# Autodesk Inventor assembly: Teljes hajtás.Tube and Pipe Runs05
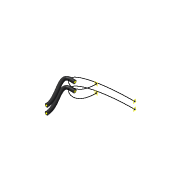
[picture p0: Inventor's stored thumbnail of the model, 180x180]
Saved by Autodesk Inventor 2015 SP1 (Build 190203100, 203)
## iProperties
Name: ISO 2531 - Flanged Ductile Iron Pipe and Fittings
ActiveState: False
PipeType: Rigid Pipe
RoutePreview: Solid
Material: UnInitValue
Standard: UnInitValue
FittingMaterial: UnInitValue
FittingStandard: UnInitValue
RouteDirection90: True
RouteDirection45: True
DiameterType: Nominal
Diameter: M40
Schedule: PN10
Ending: UnInitValue
IntermediateSegmentsMin: 1000.000 mm
IntermediateSegmentsMax: 9000.000 mm
IntermediateSegmentsInc: 10.000 mm
TerminationSegmentsMin: 1000.000 mm
TerminationSegmentsMax: 9000.000 mm
TerminationSegmentsInc: 10.000 mm
SolidRoutePreviewColor: 12632064
PipingComponentColor: As Material
PipeKey: v3#f52fbdcb-ece8-4303-8b76-5dbe8c7f2f9c#16
Elbow90Key: v3#451ae64e-c79d-4cba-b533-c09b8090ecb2#1
Elbow45Key: v3#81684a3f-f2a4-4fe6-95b1-f067ddead22f#1
_ComponentInfo: <CS><C N="Pipe" R="2.700000" IR="2.000000" PL="PL" PN="ISO 2531 Pipe with Integrally Cast Flanges DN40 PN 10"><CO N="1"><FE V="0"/><FD V="0"/><ET  V="Flanged"/>
BendRadius: UnInitValue
CategoryName: UnInitValue
DefaultBendRadius: UnInitValue
EndFittingKey: UnInitValue
FlangeKey: UnInitValue
Gap: UnInitValue
GasketKey: UnInitValue
IsButtWelded: UnInitValue
IsFlanged: UnInitValue
MixedUnits: UnInitValue
RoundUpValue: UnInitValue
ShowGap: UnInitValue
StartFittingKey: UnInitValue
SuppressEndFitting: UnInitValue
SuppressStartFitting: UnInitValue
UseFlangsForCouplings: UnInitValue
UseSubASM: UnInitValue
Name: Hydraulic Hose - SAE Flanged Connection
PipeType: Flexible Hose
RouteDirection90: UnInitValue
RouteDirection45: UnInitValue
Diameter: 1/2
Schedule: ID=0.5
OD: 2.235200000000000e+000
ID: 1.270000000000000e+000
IntermediateSegmentsMin: UnInitValue
IntermediateSegmentsMax: UnInitValue
IntermediateSegmentsInc: UnInitValue
TerminationSegmentsMin: UnInitValue
TerminationSegmentsMax: UnInitValue
TerminationSegmentsInc: UnInitValue
RoundUpValue: 0.125 in
PipeKey: v3#d489867e-ac9b-47ea-b952-0a1b885f66be#4
CouplingKey: UnInitValue
Elbow90Key: UnInitValue
Elbow45Key: UnInitValue
_ComponentInfo: <CS><C N="Pipe" R="1.117600" OR="1.117600" IR="0.635000" PL="PL" PartType="" SymKey="" PN="Parker Hydraulic Hose - No Skive 1/2"><CO N="1"><FE V="0"/><FD V="0"/
BendRadius: 0.500 in
StartFittingKey: v3#933069c9-73b6-4141-af99-628d4a97b2c2#1
EndFittingKey: v3#933069c9-73b6-4141-af99-628d4a97b2c2#1
SuppressStartFitting: False
SuppressEndFitting: False
UseSubASM: True
Name: Hydraulic Hose - Female Taper Thread
StartFittingKey: v3#cc3bd835-95a2-497d-9893-176cd9c426f6#7
EndFittingKey: v3#cc3bd835-95a2-497d-9893-176cd9c426f6#7
Name: JIS G 3458/JIS B 2316 -  Welded Steel Pipe and Fittings
Schedule: 80
IntermediateSegmentsMin: 60.000 mm
IntermediateSegmentsMax: 5000.000 mm
IntermediateSegmentsInc: 1.000 mm
TerminationSegmentsMin: 60.000 mm
TerminationSegmentsMax: 5000.000 mm
TerminationSegmentsInc: 1.000 mm
PipeKey: v3#da14b0ab-0b36-4851-8d66-8c9cd0bcbe86#23
CouplingKey: v3#12b64993-10e6-4915-8315-0c0cce209ad0#8
Elbow90Key: v3#1f65ece3-c41a-48d4-8661-909ed34ade86#8
Elbow45Key: v3#28e76e79-e22c-40ab-8be2-ff545b1407c5#8
_ComponentInfo: <CS><C N="Pipe" R="2.430000" IR="1.920000" PL="PL" PN="JIS G 3458 Pipe 40 A x Sch 80"><CO N="1"><FE V="0"/><FD V="1"/><ET V="Welded"/><NS  V="M40"/><MA V="0.000
Name: ASTM A53/A53M-ASME B16.11 - Welded Steel Pipe
Material: Steel
Standard: ASTM A 53/A 53M
FittingMaterial: Steel
FittingStandard: ASME B16.11
Schedule: 40
OD: Undefined
ID: Undefined
IntermediateSegmentsMin: 1.000 in
IntermediateSegmentsMax: 200.000 in
IntermediateSegmentsInc: 0.100 in
TerminationSegmentsMin: 1.000 in
TerminationSegmentsMax: 200.000 in
TerminationSegmentsInc: 0.100 in
PipeKey: v3#4ce5e9fa-6da0-4801-ac02-ee7a0fb518d6#7
CouplingKey: v3#ed415c76-4cec-44a3-ba67-72e47bf70384#4
Elbow90Key: v3#82a08401-12d7-413b-b7f9-9cf3b607be7b#4
Elbow45Key: v3#2e5fd082-3851-4eb0-bde1-6c7078a7d72b#4
_ComponentInfo: <CS><C N="Pipe" R="1.066800" IR="0.789940" PL="PL" PN="ASTM A 53/A 53M Pipe 1/2 - Schedule 40"><CO N="1"><FE V="0"/><FD V="0"/><ET V="Welded"/><NS  V="1/2"/><MA
Diameter: 6
Elbow90Key: v3#97ecdcaf-8aa3-4fb0-8b6a-3da783de2ad5#108
Gap: 0.062 inch
ID: UnInitValue
IntermediateSegmentsInc: 0.00001 in
IntermediateSegmentsMax: 200 inch
IntermediateSegmentsMin: 3 inch
IsButtWelded: True
IsFlanged: False
Name: ASTM A 53/A-ASME B16.9 - Steel Butt Welded Pipe
OD: UnInitValue
PipeKey: v3#4ce5e9fa-6da0-4801-ac02-ee7a0fb518d6#77
RouteDirection45: False
ShowGap: True
TerminationSegmentsInc: 0.00001 in
TerminationSegmentsMax: 200 inch
TerminationSegmentsMin: 3 inch
_ComponentInfo: <CS><C N="Elbow90" ER="15.240000" S1="15.240000" S2="15.240000" D1="0.000000" D2="0.000000" PartType="fitting" SymKey="ELBW"><CO N="1"><FE V="2"/><FD V="0"/><ET
MixedUnits: False
Created: 2013-02
Part Number: Teljes hajtás.Tube and Pipe Runs05
Document SubType Name: Tube & Pipe
Designer: Marci
Manufacturer: Standard
Standards Organization: Custom
Angle: 92.00 deg
Diameter: 1
Elbow45Key: v3#bf26aa2a-f3dd-474c-8758-922a145c2b02#15
Elbow90Key: v3#3e93288f-9bb7-4e46-9d6b-544f8c20ca1c#3
ElbowCustomKey: v3#1f3bd44a-47ab-42f9-b3e0-74afa0c3f0ca#3
Gap: 0.094 in
IntermediateSegmentsMin: 2.000 in
IsSelfDraining: True
Name: ASME BPE - Butt Welded
PipeKey: v3#b10c956f-6fc6-429e-8056-0864a8581764#35
Schedule: ID=0.87
TerminationSegmentsMin: 2.000 in
_ComponentInfo: <CS><C N="Pipe" R="1.270000" OR="1.270000" IR="1.104900" PL="PL" PartType="pipe" SymKey="" PN="ASTM A 269 Tube with Welded ends 1 x 0.87"><CO N="1"><FE V="2"/><
Elbow90Key: v3#6a678020-d9d9-4685-bba9-906b9a167083#10
FlangeKey: v3#c11442d2-c568-438f-a870-8ac9b5b636cb#10
GasketKey: v3#2a41914c-f5fb-4682-9c6a-1870d826d3d0#23
IntermediateSegmentsInc: 0.1 inch
IsButtWelded: False
IsFlanged: True
Name: ASTM A 53/A-ASME B16.5 - Flanged Steel Threaded Pipe
PipeKey: v3#c5bd7d28-cdb3-4507-9f3d-c2787d93fe8a#40
TerminationSegmentsInc: 0.1 inch
_ComponentInfo: <CS><C N="Elbow90" ER="21.590000" S1="21.590000" S2="21.590000" D1="0.000000" D2="0.000000" PartType="fitting" SymKey="ELFL"><CO N="1"><FE V="2"/><FD V="1"/><ET
ElbowCustomKey: UnInitValue
IsSelfDraining: False
Name: ASME B36.10M-ASME B16.11 - Steel Threaded Pipe
Material: Wrought Steel
Standard: ASME B36.10M
Schedule: 30
OD: 2.1336
ID: 1.651
PipeKey: v3#4a736116-503a-44ad-a922-868ac6b46736#1
CouplingKey: v3#52ad3977-2b89-4007-a6a6-7626bac0ae85#4
Elbow90Key: v3#160eac10-3e6f-4b5c-839c-61eee0d373dc#4
Elbow45Key: v3#5c2ab816-abcb-49a6-a106-4733af000f51#4
_ComponentInfo: <CS><C N="Pipe" R="1.066800" IR="0.825500" PL="PL" PN="ASME B36.10M Pipe with Threaded Ends 1/2 - Schedule 30"><CO N="1"><FE V="0"/><FD V="1"/><ET  V="Threaded"
Name: DIN 2458/DIN 2605 - Welded Steel Pipe and Fittings
Schedule: ID=30.7
PipeKey: v3#dcef2839-8903-4c98-a96c-b861f5d9bb7f#98
Elbow90Key: v3#ace818b0-7b7c-4ad9-b19c-6da358a202c1#17
Elbow45Key: v3#97879d80-057e-491b-840b-74a9b3a7cf63#17
_ComponentInfo: <CS><C N="Pipe" R="2.415000" IR="1.535000" PL="PL" PN="DIN 2458 Pipe 48.3 x 8.8"><CO N="1"><FE V="2"/><FD V="0"/><ET V="Welded"/><NS V="M40"/><MA  V="0.000000"/
Name: Hydraulic Hose - Male Taper Thread
StartFittingKey: v3#c8250148-a7b6-458b-b7bd-3b56763ca7cc#13
EndFittingKey: v3#c8250148-a7b6-458b-b7bd-3b56763ca7cc#13
Name: JIS G 3442/JIS B 2301 Threaded Steel Pipe and Iron Fittings
Schedule: ID=16.1
IntermediateSegmentsMin: 20.000 mm
TerminationSegmentsMin: 20.000 mm
PipeKey: v3#9964fba4-9d5a-4d75-85a8-e38022ccdce1#2
CouplingKey: v3#181262db-c004-4877-bc40-c64b931a44f6#3
Elbow90Key: v3#6c92b367-65e9-486b-b952-db434ae2548d#3
Elbow45Key: v3#960407aa-00b9-4d72-aae7-d50595845cfd#3
_ComponentInfo: <CS><C N="Pipe" R="1.085000" IR="0.805000" PL="PL" PN="JIS G 3442 Pipe with Threaded Ends 21.7 x 2.8"><CO N="1"><FE V="0"/><FD V="1"/><ET V="Threaded"/><NS V="1
Name: ASTM B 88-ASME B16.22 - Soldered Copper Tubing
PipeType: Tubing
Material: Copper
Standard: ASTM B 88
FittingMaterial: *
FittingStandard: ASME B16.22
Schedule: L
IntermediateSegmentsMin: 0.000 in
IntermediateSegmentsMax: 100.000 in
TerminationSegmentsMin: 0.000 in
TerminationSegmentsMax: 100.000 in
SolidRoutePreviewColor: 49344
PipeKey: v3#44b182c9-4bce-4825-bb4d-596143122252#7
CouplingKey: v3#0dc1ae02-7bbf-4ccf-8498-581434b0a765#3
_ComponentInfo: <CS><C N="Pipe" R="0.793750" IR="0.692150" PL="PL" PN="ASTM B 88 Tube 1/2 - Type L"><CO N="1"><FE V="0"/><FD V="0"/><ET V="Soldered"/><NS V="1/2"/><MA V="2.5400
DefaultBendRadius: 2.000 in
Name: JIS K 6741/JIS K 6739 - Jointed PVC-U Pipe and Fittings
Schedule: VP
IntermediateSegmentsMax: 2500.000 mm
TerminationSegmentsMax: 2500.000 mm
PipeKey: v3#45338dd0-af69-48c0-a2ed-8ade33a08701#5
CouplingKey: v3#eaa8de87-dc67-4eca-ba7e-4267a30f8f7f#2
Elbow90Key: v3#c4513a61-3106-4a78-baf9-a1badd100245#2
Elbow45Key: v3#2769403e-a4fd-4a4c-8e4c-659ea845bd78#2
_ComponentInfo: <CS><C N="Pipe" R="2.400000" IR="2.040000" PL="PL" PN="JIS K 6741 Pipe VP 40"><CO N="1"><FE V="0"/><FD V="1"/><ET V="Jointed"/><NS V="M40"/><MA  V="4.000000"/><
Name: ISO 7598/ISO 49 - Threaded Steel Pipe with Iron Fittings
IntermediateSegmentsMin: 50.800 mm
IntermediateSegmentsMax: 5080.000 mm
IntermediateSegmentsInc: 2.540 mm
TerminationSegmentsMin: 50.800 mm
TerminationSegmentsMax: 5080.000 mm
TerminationSegmentsInc: 2.540 mm
PipeKey: v3#1052637f-74b5-47f4-adeb-d4e8d3fa53b8#1
CouplingKey: v3#7e56b2cb-a132-4546-b8a7-a14538454b94#3
Elbow90Key: v3#b72bb08b-ad33-47cc-a03d-7f3d76c6616b#3
Elbow45Key: v3#a96c5204-26e4-4bb2-b8f1-f0623fbc94bb#2
_ComponentInfo: <CS><C N="Pipe" R="1.065000" IR="0.805000" PL="PL" PN="ISO 7598 Tube with Threaded Ends DN15"><CO N="1"><FE V="0"/><FD V="1"/><ET V="Threaded"/><NS V="1/2"/><MA
FlangeKey: v3#24991861-26e3-4c21-a713-f46e314eddd5#10
IntermediateSegmentsMin: 3.000 in
Name: ASTM A 53/A 53M - Butt Welded/Flanged Steel Pipe
TerminationSegmentsMin: 3.000 in
UseFlangsForCouplings: False
_ComponentInfo: <CS><C N="Pipe" R="8.413750" OR="8.413750" IR="7.702550" PL="PL" PartType="pipe" SymKey="" PN="ASTM A 53/A 53M Pipe 6 - Schedule 40"><CO N="1"><FE V="2"/><FD V=
Name: Hydraulic Hose - Female Thread - Swivel
StartFittingKey: v3#c5e461f5-5e73-4f2e-8c1e-4358d4d6f46c#4
EndFittingKey: v3#c5e461f5-5e73-4f2e-8c1e-4358d4d6f46c#4
Name: ASTM D 1785-ASTM D 2466 - Jointed PVC Pipe and Fittings
Material: PVC-Piping
Standard: ASTM D 1785
FittingMaterial: PVC-Piping
FittingStandard: ASTM D 2466
PipeKey: v3#4bf12049-4375-491b-8f13-d4ee0c517c57#1
CouplingKey: v3#29993622-4c6a-437e-8b8c-43a0846f8735#1
Elbow90Key: v3#25d2a8db-6517-4627-a5a4-9d27e4d26b9b#1
Elbow45Key: v3#d7b5d569-4a12-4d65-ba55-12203d6ac7ed#1
_ComponentInfo: <CS><C N="Pipe" R="1.066800" IR="0.789940" PL="PL" PN="ASTM D 1785 Pipe 1/2 - Schedule 40"><CO N="1"><FE V="0"/><FD V="0"/><ET V="Jointed"/><NS  V="1/2"/><MA V=
Name: DIN 2458/DIN EN 10242 - Threaded Steel Pipe and Iron Fittings
Schedule: ID=12.3
PipeKey: v3#d689fd5f-ac5a-46d7-a883-3089b2f6e0a4#28
CouplingKey: v3#d2599e7a-1865-48da-a234-5418a1cd5dfe#3
Elbow90Key: v3#9fba244e-81ed-4fc6-a9ac-7eb372fa3ffe#3
Elbow45Key: v3#6ce5b1be-37aa-4928-b23a-0df64e6ddf38#2
_ComponentInfo: <CS><C N="Pipe" R="1.065000" IR="0.615000" PL="PL" PN="DIN 2458 Pipe with Threaded Ends 21.3 x 4.5"><CO N="1"><FE V="0"/><FD V="1"/><ET V="Threaded"/><NS V="1/2
count: 29
Refkey_Axis1_Context: 2|0|0|0|1|0|0|0|
Refkey_Axis1: 6|0|0|0|44|0|0|0|78|0|65|0|77|0|69|0|83|0|10|0|67|0|111|0|108|0|111|0|114|0|115|0|10|0|49|0|58|0|10|0|10|0|69|0|78|0|68|0|10|0|0|0|
Refkey_Axis2_Context: 2|0|0|0|1|0|0|0|
Refkey_Axis2: 6|0|0|0|88|0|0|0|78|0|65|0|77|0|69|0|83|0|10|0|67|0|111|0|108|0|111|0|114|0|115|0|10|0|49|0|58|0|82|0|111|0|117|0|116|0|101|0|32|0|85|0|73|0|32|0|84|0|111|0|111
Refkey_Axis3_Context: 2|0|0|0|1|0|0|0|
Refkey_Axis3: 6|0|0|0|88|0|0|0|78|0|65|0|77|0|69|0|83|0|10|0|67|0|111|0|108|0|111|0|114|0|115|0|10|0|49|0|58|0|82|0|111|0|117|0|116|0|101|0|32|0|85|0|73|0|32|0|84|0|111|0|111
Refkey_Ext_Context: 2|0|0|0|1|0|0|0|
Refkey_Ext: 6|0|0|0|92|0|0|0|78|0|65|0|77|0|69|0|83|0|10|0|67|0|111|0|108|0|111|0|114|0|115|0|10|0|49|0|58|0|82|0|111|0|117|0|116|0|101|0|32|0|85|0|73|0|32|0|84|0|111|0|111
Refkey_Snap_Context: 2|0|0|0|1|0|0|0|
Refkey_Snap: 6|0|0|0|84|0|0|0|78|0|65|0|77|0|69|0|83|0|10|0|67|0|111|0|108|0|111|0|114|0|115|0|10|0|49|0|58|0|82|0|111|0|117|0|116|0|101|0|32|0|85|0|73|0|32|0|84|0|111|0|111
Name: DIN 8062/DIN 8063 - Jointed PVC-U Pipe and Fittings
Schedule: 5
PipeKey: v3#3d294dc7-89c3-4c37-a0ae-28c15a73bfd0#13
CouplingKey: v3#3edf83e2-464b-4b31-84c5-c329ffbf2a4f#5
Elbow90Key: v3#fbd68fd5-590c-4cb5-8c20-9e9bdd396a04#5
Elbow45Key: v3#2f597a97-b15b-49d4-87cb-7bfe69eb62ee#5
_ComponentInfo: <CS><C N="Pipe" R="2.000000" IR="1.700000" PL="PL" PN="DIN 8062 Pipe 40 x 3"><CO N="1"><FE V="0"/><FD V="0"/><ET V="Jointed"/><NS V="M40"/><MA  V="8.000000"/><M
Name: ANSI/ASME B36.19M-ASME B16.3 - Threaded Pipe with Iron Fittings
Material: Stainless Steel
Standard: ANSI/ASME B36.19M
FittingMaterial: Malleable Iron
FittingStandard: ASME B16.3
Schedule: 40S
PipeKey: v3#323c0148-c750-449d-a0c6-11721f2a5046#1
CouplingKey: v3#771d4942-b9e7-43bc-9d41-ab12a9580492#3
Elbow90Key: v3#bc6b44ab-9235-4590-b699-74498030a1ff#3
Elbow45Key: v3#626cc28c-1a24-4045-be0d-40d896dc828d#3
_ComponentInfo: <CS><C N="Pipe" R="1.066800" IR="0.789940" PL="PL" PN="ANSI/ASME B36.19M Pipe with Threaded Ends 1/2 - Schedule 40S"><CO N="1"><FE V="0"/><FD  V="1"/><ET V="Thr
Name: Hydraulic Hose - Male Straight Thread
StartFittingKey: v3#b50cb43e-68c0-48ac-8e25-7ef224ce0e6c#3
EndFittingKey: v3#b50cb43e-68c0-48ac-8e25-7ef224ce0e6c#3
Name: ISO 4065-ISO 3633 - PVC Pipe and Fittings
Schedule: S40
IntermediateSegmentsMax: 2540.000 mm
TerminationSegmentsMax: 2540.000 mm
PipeKey: v3#4f84f716-5ba0-45ef-967a-c32c3d7345ce#70
CouplingKey: v3#b06656e5-2b55-488c-bcf0-6a90c79c4683#2
Elbow90Key: v3#17490b17-1dd8-40fc-8de7-1a70c3bab2d7#1
Elbow45Key: v3#421a8b99-1721-409a-bc3b-c00889561754#1
_ComponentInfo: <CS><C N="Pipe" R="2.000000" IR="1.950000" PL="PL" PN="ISO 4065 Pipe 40 x 0.5 S40"><CO N="1"><FE V="0"/><FD V="0"/><ET V="Jointed"/><NS V="M40"/><MA  V="6.00000
Name: Hydraulic Hose - No Fittings
ActiveState: True
Diameter: 1/4
Schedule: ID=0.25
OD: 1,4986
ID: 0,635
PipingComponentColor: Blue - Wall Paint - Glossy
PipeKey: v3#d489867e-ac9b-47ea-b952-0a1b885f66be#1
_ComponentInfo: <CS><C N="Pipe" R="0,749300" OR="0,749300" IR="0,317500" PL="PL" PartType="pipe" SymKey="" PN="Parker hidraulikatömlő - No Skive 1/4"><CO N="1"><FE V="0"/><FD V
SuppressStartFitting: True
SuppressEndFitting: True
Angle: UnInitValue
IsSelfDraining: UnInitValue
USE_R9_BOM: False
Author: Marci
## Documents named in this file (2)
- C:\Users\TREINA11\Desktop\#01- Polymechanics and Automation\01 - 3D Models\Pneumatic System\Teljes hajtás.Tube and Pipe Runs05.iam
- C:\Users\TREINA11\Desktop\#01- Polymechanics and Automation\01 - 3D Models\Pneumatic System\Teljes hajtás.Run07.iam
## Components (1 placed, 1 different names)
1. Run06 [sub-assembly]
